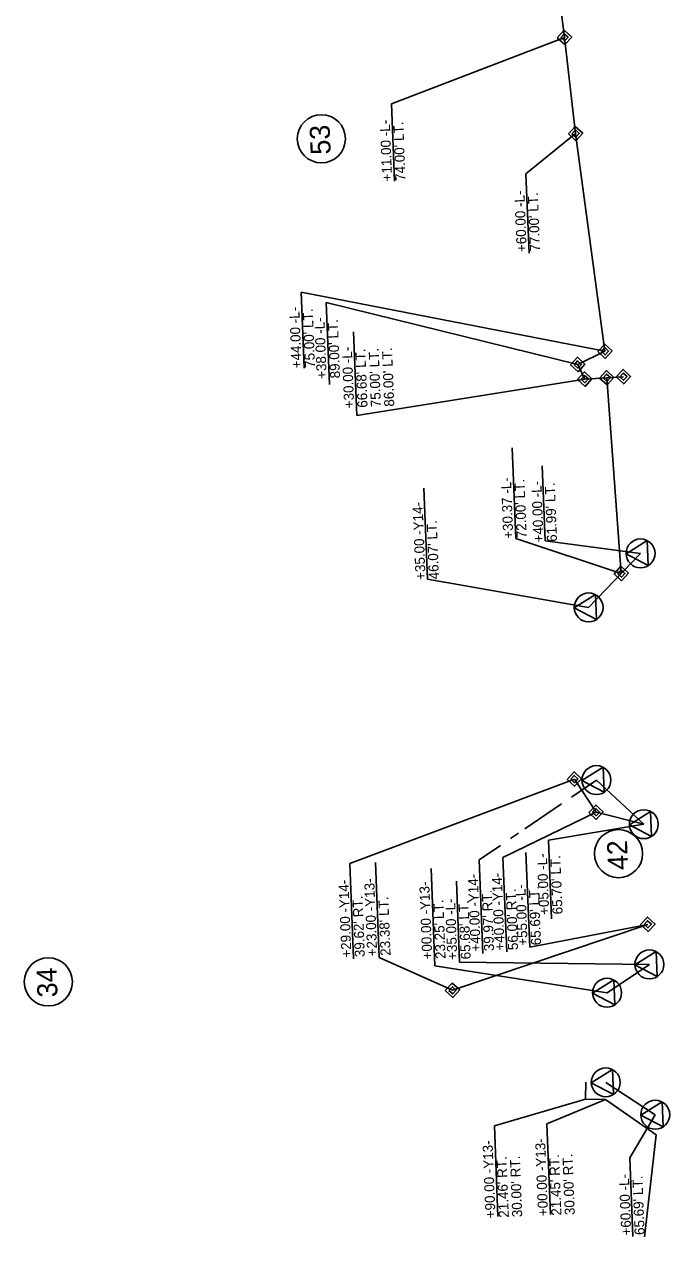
# Model space of a CAD drawing. Extents: x 1627970 to 1628801, y 761752 to 765698.
# Drawn here: x 1628006 to 1628328, y 764570 to 765175 of the extents above; entities that cross this region are included whole.
import ezdxf

# ---------------------------------------------------------------- set-up
doc = ezdxf.new("R2010")
doc.units = 0
for name, color, linetype in [('Exist Other Culture Gas Pump or Vent CELL', 7, 'Continuous'), ('Exist Property Line Leader', 7, 'Continuous'), ('Exist Property Line Text', 7, 'Continuous'), ('Exist Property Owner Number CELL', 7, 'Continuous'), ('Exist Right of Way Control of Access Line', 7, 'Continuous'), ('Exist Right of Way Monument Leader', 7, 'Continuous'), ('Exist Right of Way Monument Text', 7, 'Continuous'), ('Exist Roads EOT', 7, 'Continuous'), ('Exist Utilities Gas UG Line', 7, 'Continuous'), ('Exist Utilities Gas UG Line Text', 7, 'Continuous'), ('Exist Utilities Other Unknown UG SUE Text', 7, 'Continuous')]:
    doc.layers.add(name, color=color, linetype=linetype)

msp = doc.modelspace()

# ---------------------------------------------------------------- linework, layer by layer
at = {"layer": 'Exist Other Culture Gas Pump or Vent CELL'}
for p, q in [((1628249.42, 764963.43), (1628251.21, 764918.27)), ((1628251.21, 764918.27), (1628303.81, 764900.8))]:
    msp.add_line(p, q, dxfattribs=at)
at = {"layer": 'Exist Property Line Leader'}
for p, q in [((1628281.03, 765120.19), (1628275.51, 765168.16)), ((1628282.12, 765005), (1628295.68, 765011.63)), ((1628285.61, 764997.73), (1628282.12, 765005)), ((1628304.88, 764998.95), (1628285.61, 764997.73)), ((1628291.22, 764781.74), (1628280.43, 764798.26)), ((1628315.04, 764775.77), (1628291.22, 764781.74)), ((1628219.72, 764692.94), (1628317.02, 764725.81))]:
    msp.add_line(p, q, dxfattribs=at)
for points in [[(1628275.51, 765168.16), (1628259.21, 765296.59), (1628235.32, 765456.66)], [(1628295.68, 765011.63), (1628281.03, 765120.19)]]:
    msp.add_lwpolyline(points, dxfattribs=at)
at = {"layer": 'Exist Property Line Text'}
for p, q in [((1628154.35, 765117.59), (1628154.35, 765117.59)), ((1628302.44, 764761.08), (1628302.44, 764761.08)), ((1628018.28, 764697.12), (1628018.28, 764697.12))]:
    msp.add_line(p, q, dxfattribs=at)
for centre in [(1628154.35, 765117.59), (1628302.44, 764761.08), (1628018.28, 764697.12)]:
    msp.add_circle(centre, 12, dxfattribs=at)
at = {"layer": 'Exist Property Owner Number CELL'}
msp.add_line((1628303.81, 764900.8), (1628296.58, 764998.42), dxfattribs=at)
at = {"layer": 'Exist Right of Way Control of Access Line'}
for p, q in [((1628287.55, 764883.87), (1628313.42, 764910.82)), ((1628315.04, 764775.77), (1628291.43, 764797.77)), ((1628296.71, 764691.72), (1628317.82, 764705.83)), ((1628320.76, 764630.89), (1628296.07, 764647.02))]:
    msp.add_line(p, q, dxfattribs=at)
at = {"layer": 'Exist Right of Way Monument Leader'}
for points in [[(1628271.91, 765168.01), (1628275.36, 765171.75), (1628279.1, 765168.3), (1628275.65, 765164.56)], [(1628273.71, 765168.08), (1628275.43, 765169.95), (1628277.3, 765168.23), (1628275.58, 765166.36)], [(1628277.43, 765120.05), (1628280.89, 765123.79), (1628284.63, 765120.33), (1628281.17, 765116.6)], [(1628279.23, 765120.12), (1628280.96, 765121.99), (1628282.83, 765120.26), (1628281.1, 765118.39)], [(1628292.08, 765011.48), (1628295.54, 765015.22), (1628299.27, 765011.77), (1628295.82, 765008.03)], [(1628293.88, 765011.56), (1628295.61, 765013.42), (1628297.48, 765011.7), (1628295.75, 765009.83)], [(1628278.52, 765004.86), (1628281.97, 765008.6), (1628285.71, 765005.14), (1628282.26, 765001.4)], [(1628280.32, 765004.93), (1628282.05, 765006.8), (1628283.91, 765005.07), (1628282.19, 765003.2)], [(1628282.01, 764997.59), (1628285.46, 765001.32), (1628289.2, 764997.87), (1628285.75, 764994.13)], [(1628292.99, 764998.28), (1628296.44, 765002.02), (1628300.18, 764998.57), (1628296.73, 764994.83)], [(1628301.29, 764998.81), (1628304.74, 765002.55), (1628308.48, 764999.09), (1628305.03, 764995.35)], [(1628303.09, 764998.88), (1628304.81, 765000.75), (1628306.68, 764999.02), (1628304.95, 764997.15)], [(1628283.81, 764997.66), (1628285.53, 764999.53), (1628287.4, 764997.8), (1628285.68, 764995.93)], [(1628294.78, 764998.35), (1628296.51, 765000.22), (1628298.38, 764998.49), (1628296.65, 764996.62)], [(1628300.21, 764900.66), (1628303.66, 764904.4), (1628307.4, 764900.94), (1628303.95, 764897.2)], [(1628302.01, 764900.73), (1628303.74, 764902.6), (1628305.6, 764900.87), (1628303.88, 764899)], [(1628276.84, 764798.12), (1628280.29, 764801.86), (1628284.03, 764798.4), (1628280.58, 764794.66)], [(1628278.64, 764798.19), (1628280.36, 764800.06), (1628282.23, 764798.33), (1628280.51, 764796.46)], [(1628287.62, 764781.6), (1628291.08, 764785.34), (1628294.82, 764781.88), (1628291.36, 764778.14)], [(1628289.42, 764781.67), (1628291.15, 764783.54), (1628293.02, 764781.81), (1628291.29, 764779.94)], [(1628313.43, 764725.67), (1628316.88, 764729.41), (1628320.62, 764725.96), (1628317.17, 764722.22)], [(1628315.23, 764725.74), (1628316.95, 764727.61), (1628318.82, 764725.88), (1628317.1, 764724.01)], [(1628216.12, 764692.8), (1628219.58, 764696.54), (1628223.31, 764693.08), (1628219.86, 764689.34)], [(1628217.92, 764692.87), (1628219.65, 764694.74), (1628221.52, 764693.01), (1628219.79, 764691.14)]]:
    msp.add_lwpolyline(points, close=True, dxfattribs=at)
at = {"layer": 'Exist Right of Way Monument Text'}
for p, q in [((1628285.95, 764638.61), (1628286.07, 764647.16)), ((1628295.95, 764638.47), (1628285.95, 764638.61)), ((1628321.16, 764620.9), (1628295.95, 764638.47))]:
    msp.add_line(p, q, dxfattribs=at)
at = {"layer": 'Exist Roads EOT'}
for p, q in [((1628189.31, 765134.96), (1628275.51, 765168.16)), ((1628189.31, 765134.96), (1628190.82, 765096.51)), ((1628256.26, 765100.15), (1628281.03, 765120.19)), ((1628256.26, 765100.15), (1628257.83, 765060.57)), ((1628295.68, 765011.63), (1628144.21, 765041.13)), ((1628144.21, 765041.13), (1628145.71, 765003.27)), ((1628156.71, 765036), (1628158.33, 764994.97)), ((1628282.12, 765005), (1628156.71, 765036)), ((1628170.4, 765021.36), (1628172.04, 764979.65)), ((1628285.61, 764997.73), (1628172.04, 764979.65)), ((1628280.43, 764798.26), (1628168.45, 764756.09)), ((1628291.22, 764781.74), (1628244.86, 764759.21)), ((1628244.86, 764759.21), (1628246.72, 764712.09)), ((1628256.3, 764761.62), (1628258.16, 764714.5)), ((1628168.45, 764756.09), (1628170.32, 764708.6)), ((1628181.29, 764756.74), (1628183.16, 764709.25)), ((1628317.02, 764725.81), (1628258.16, 764714.5)), ((1628219.72, 764692.94), (1628183.16, 764709.25))]:
    msp.add_line(p, q, dxfattribs=at)
at = {"layer": 'Exist Utilities Gas UG Line'}
for p, q in [((1628264.43, 764954.47), (1628265.91, 764917.04)), ((1628205.45, 764943.42), (1628207.24, 764897.9)), ((1628313.42, 764910.82), (1628265.91, 764917.04)), ((1628287.55, 764883.87), (1628207.27, 764897.9)), ((1628278.96, 764789.28), (1628291.43, 764797.77)), ((1628255.76, 764773.47), (1628273.95, 764785.86)), ((1628248.63, 764768.61), (1628252.54, 764771.28)), ((1628267.48, 764767.84), (1628315.04, 764775.77)), ((1628233.02, 764757.99), (1628243.54, 764765.15)), ((1628267.48, 764767.84), (1628269.02, 764728.56)), ((1628209.01, 764753.64), (1628210.93, 764705.07)), ((1628233.02, 764757.99), (1628234.87, 764711.29)), ((1628221.65, 764747.29), (1628223.23, 764707.01)), ((1628210.93, 764705.07), (1628296.71, 764691.72)), ((1628317.82, 764705.83), (1628223.23, 764707.01)), ((1628308.03, 764609.35), (1628320.76, 764630.89)), ((1628308.03, 764609.35), (1628309.58, 764570.07))]:
    msp.add_line(p, q, dxfattribs=at)
at = {"layer": 'Exist Utilities Gas UG Line Text'}
for p, q in [((1628285.95, 764638.61), (1628240.55, 764625.32)), ((1628295.95, 764638.47), (1628266.75, 764626.35)), ((1628266.75, 764626.35), (1628268.53, 764581.19)), ((1628240.55, 764625.32), (1628242.33, 764580.16)), ((1628321.16, 764620.9), (1628315.34, 764569.97))]:
    msp.add_line(p, q, dxfattribs=at)
at = {"layer": 'Exist Utilities Other Unknown UG SUE Text'}
for p, q in [((1628275.51, 765168.16), (1628275.51, 765168.16)), ((1628281.03, 765120.19), (1628281.03, 765120.19)), ((1628295.68, 765011.63), (1628295.68, 765011.63)), ((1628282.12, 765005), (1628282.12, 765005)), ((1628285.61, 764997.73), (1628285.61, 764997.73)), ((1628296.58, 764998.42), (1628296.58, 764998.42)), ((1628304.88, 764998.95), (1628304.88, 764998.95)), ((1628313.42, 764910.82), (1628313.42, 764910.82)), ((1628303.81, 764900.8), (1628303.81, 764900.8)), ((1628287.55, 764883.87), (1628287.55, 764883.87)), ((1628280.43, 764798.26), (1628280.43, 764798.26)), ((1628291.43, 764797.77), (1628291.43, 764797.77)), ((1628291.22, 764781.74), (1628291.22, 764781.74)), ((1628315.04, 764775.77), (1628315.04, 764775.77)), ((1628317.02, 764725.81), (1628317.02, 764725.81)), ((1628317.82, 764705.83), (1628317.82, 764705.83)), ((1628219.72, 764692.94), (1628219.72, 764692.94)), ((1628296.71, 764691.72), (1628296.71, 764691.72)), ((1628296.07, 764647.02), (1628296.07, 764647.02)), ((1628320.76, 764630.89), (1628320.76, 764630.89))]:
    msp.add_line(p, q, dxfattribs=at)
for points in [[(1628306.22, 764910.55), (1628316.78, 764917.18), (1628317.27, 764904.72)], [(1628280.34, 764883.6), (1628290.9, 764890.24), (1628291.4, 764877.77)], [(1628284.22, 764797.5), (1628294.79, 764804.13), (1628295.28, 764791.67)], [(1628307.83, 764775.5), (1628318.4, 764782.14), (1628318.89, 764769.67)], [(1628310.61, 764705.56), (1628321.18, 764712.2), (1628321.67, 764699.73)], [(1628289.5, 764691.45), (1628300.07, 764698.09), (1628300.56, 764685.62)], [(1628288.87, 764646.75), (1628299.43, 764653.39), (1628299.92, 764640.92)], [(1628313.55, 764630.62), (1628324.12, 764637.26), (1628324.61, 764624.79)]]:
    msp.add_lwpolyline(points, close=True, dxfattribs=at)
for centre in [(1628313.42, 764910.82), (1628287.55, 764883.87), (1628291.43, 764797.77), (1628315.04, 764775.77), (1628317.82, 764705.83), (1628296.71, 764691.72), (1628296.07, 764647.02), (1628320.76, 764630.89)]:
    msp.add_circle(centre, 7.2, dxfattribs=at)

# ---------------------------------------------------------------- texts
at = {"layer": 'Exist Other Culture Gas Pump or Vent CELL'}
for s, p in [('+30.37 -L-', (1628250.03, 764918.21)), ("72.00' LT.", (1628256.69, 764918.47))]:
    msp.add_text(s, height=5, rotation=92.25819, dxfattribs=at).set_placement(p)
at = {"layer": 'Exist Property Line Text'}
for s, p in [('53', (1628159.03, 765109.86)), ('42', (1628307.23, 764753.12)), ('34', (1628022.89, 764689.58))]:
    msp.add_text(s, height=10, rotation=92.25819, dxfattribs=at).set_placement(p)
at = {"layer": 'Exist Roads EOT'}
for s, p in [('+11.00 -L-', (1628189.65, 765096.45)), ("74.00' LT.", (1628196.31, 765096.71)), ('+60.00 -L-', (1628256.7, 765061.2)), ("77.00' LT.", (1628263.36, 765061.46)), ('+44.00 -L-', (1628144.53, 765003.2)), ("75.00' LT.", (1628151.19, 765003.47)), ('+38.00 -L-', (1628157.03, 764997.94)), ("89.00' LT.", (1628163.69, 764998.21)), ('+30.00 -L-', (1628170.72, 764983.3)), ("75.00' LT.", (1628184.04, 764983.83)), ("86.00' LT.", (1628190.7, 764984.09)), ("66.68' LT.", (1628177.38, 764983.57)), ('+29.00 -Y14-', (1628169.36, 764709.34)), ('+23.00 -Y13-', (1628182.2, 764709.98)), ('+40.00 -Y14-', (1628245.76, 764712.82)), ("56.00' RT.", (1628252.42, 764713.09)), ('+55.00 -L-', (1628257.19, 764715.23)), ("65.69' LT.", (1628263.85, 764715.49)), ("39.62' RT.", (1628176.02, 764709.6)), ("23.38' LT.", (1628188.86, 764710.25))]:
    msp.add_text(s, height=5, rotation=92.25819, dxfattribs=at).set_placement(p)
at = {"layer": 'Exist Utilities Gas UG Line'}
for s, p in [('+40.00 -L-', (1628265.15, 764916.39)), ("61.99' LT.", (1628271.82, 764916.66)), ('+35.00 -Y14-', (1628206.3, 764897.71)), ("46.07' LT.", (1628212.97, 764897.97)), ('+05.00 -L-', (1628267.92, 764730.62)), ("65.70' LT.", (1628274.58, 764730.89)), ('+00.00 -Y13-', (1628209.62, 764708.42)), ('+40.00 -Y14-', (1628233.8, 764712.28)), ("39.97' RT.", (1628240.46, 764712.54)), ("23.25' LT.", (1628216.28, 764708.68)), ('+35.00 -L-', (1628222.16, 764708.18)), ("65.68' LT.", (1628228.82, 764708.45)), ('+60.00 -L-', (1628308.82, 764570.75)), ("65.69' LT.", (1628315.48, 764571.02))]:
    msp.add_text(s, height=5, rotation=92.25819, dxfattribs=at).set_placement(p)
at = {"layer": 'Exist Utilities Gas UG Line Text'}
for s, p in [('+90.00 -Y13-', (1628241.15, 764579.35)), ('+00.00 -Y13-', (1628267.35, 764580.39)), ("21.46' RT.", (1628247.81, 764579.62)), ("30.00' RT.", (1628254.48, 764579.88)), ("21.45' RT.", (1628274.01, 764580.65)), ("30.00' RT.", (1628280.67, 764580.91))]:
    msp.add_text(s, height=5, rotation=92.25819, dxfattribs=at).set_placement(p)

doc.saveas('drawing.dxf')
